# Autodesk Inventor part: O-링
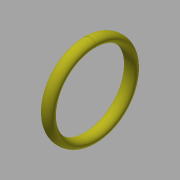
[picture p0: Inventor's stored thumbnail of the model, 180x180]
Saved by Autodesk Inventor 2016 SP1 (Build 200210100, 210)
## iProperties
Created: 2019-02
Part Number: O-링
Material: 고무
Document SubType Name: Modeling
Designer: mduedu
Density: 1 g/cm^3
Appearance: 밝은 황색
Author: mduedu
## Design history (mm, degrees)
sketch "스케치1"
  geometry: L1 (-2.35, 0)-(2.35, 0); L2 (2.35, 0)-(2.35, 17); L3 (2.35, 17)-(-2.35, 17); L4 (-2.35, 17)-(-2.35, 0); L5 (-2.35, 14)-(2.35, 14); 3 further points; 1 other entity
  constraints: 10 end point, 4 horizontal, 2 parallel, 2 perpendicular, 2 point on line, 2 vertical, 1 coincident, 1 midpoint, 2 other
  dimensions: "d0" = 34 diameter of L3 L1; "d2" = 4.7 distance of L2.end L3.end; "d3" = 28 diameter of L5 L1
revolve "회전1" sketch "스케치1" stored, may be unused: angle "d4" = 90 deg
node "솔리드1"
